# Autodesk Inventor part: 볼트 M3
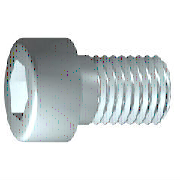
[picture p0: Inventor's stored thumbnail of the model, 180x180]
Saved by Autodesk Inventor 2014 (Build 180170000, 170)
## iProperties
IsCustomPart: 0
Created: 2012-02
Part Number: 볼트 M3
Material: 스테인리스강
Description: 6각 소켓 머리 캡 나사
Document SubType Name: Modeling
Standard: ISO 4762
Designer: mduedu
Standard Revision: Fourth edition 2004-03-01
Standards Organization: ISO
Language: ko-KR
Size Designation: M3 x 8
Categories: <MemberInstance><Categories><Category DisplayName="조임쇠" InternalName="e4da775c-781d-43d5-af7c-5136215cf5a6" Mnemonic="FSTN"><Category DisplayName="볼트" InternalN
Density: 7.75 g/cm^3
Appearance: 반광택
Author: mduedu
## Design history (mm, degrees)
sketch "스케치1"
  geometry: L1 (-0.867, 0)-(8, 0); L2 (8, 0)-(8, 1.5); L3 (8, 1.5)-(1.25, 1.5); L4 (1.25, 1.5)-(0.943, 1.5); L5 (0.943, 1.5)-(0, 1.5); L6 (0, 1.5)-(0, 2.75); L7 (0, 2.75)-(-3, 2.75); L8 (-3, 2.75)-(-3, 1.443); L9 (-3, 1.443)-(-1.7, 1.443); L10 (-1.7, 1.443)-(-0.867, 0); L11 (-5.2, 0)-(10.2, 0) reference; L12 (0, -0.55)-(0, 3.3) reference; L13 (1.25, 1.5)-(0, 1.5)
  constraints: 22 end point, 6 parallel, 2 collinear, 2 perpendicular, 1 horizontal, 1 point on line
  dimensions: "d1" = 6.75 distance from line of L3.end L2 (= GEL); "d2" = 0.30683 distance of L4.end L3.end (computed from GAL); "d3" = 3 distance between parallel lines of L8 L6 (= KOH); "d4" = 1.3 distance of L8.end L9.end (= INTI); "d5" = 60 deg angle of L10 L1; "d6" = 3 diameter of L3 L1 (= GD); "d7" = 3 diameter of L5 L1 (= BDM); "d8" = 2.88675 diameter of L9 L1 (= 1.1547 x SW); "d9" = 5.5 diameter of L7 L1 (= KOD); "d26" = 8 distance between parallel lines of L12 L2 (= NLG)
revolve "본체" sketch "스케치1" stored, may be unused: angle "d10" = 90 deg
sketch "스케치2"
  geometry: L1 (0, -3.85)-(0, 3.85) reference; L2 (-3.85, 0)-(3.85, 0) reference; L3 (1.443, 0)-(0.722, -1.25); L4 (0.722, -1.25)-(-0.722, -1.25); L5 (-0.722, -1.25)-(-1.443, 0); L6 (-1.443, 0)-(-0.722, 1.25); L7 (-0.722, 1.25)-(0.722, 1.25); L8 (0.722, 1.25)-(1.443, 0); 2 further points
  constraints: 12 end point, 1 coincident, 1 horizontal alignment, 1 point on line, 12 other
extrude "슬롯" join sketch "스케치2" stored distance "d11" = 10; taper "d12" = 0 deg
workplane "Work Plane1"
fillet "Fillet2" dims "d30" = 0.1 (= R)
body "Solid1"
fillet "모깎기1" dims "d17" = 0.3 (= RR)
feature "스레드" dims "d13" = 6.75 (= GEL), "d14" = 0
chamfer "모따기1" distance "d15" = 0.30673 (= -0.5 x SPD + 0.5 x GD); stored, may be unused: second distance "d16" = 0.30673 (= GUL), angle "d27" = 45 deg
other parameters: "GD" = 3 [user parameter; used in 2 equation terms], "NLG" = 8 [user parameter; used in 1 equation term], "GEL" = 6.75 [user parameter; used in 2 equation terms], "KOD" = 5.5 [user parameter; used in 1 equation term], "KOH" = 3 [user parameter; used in 1 equation term], "INTI" = 1.3 [user parameter; used in 1 equation term], "GAL" = 0.30673 (= 0.61345 x PTC) [user parameter; used in 1 equation term], "GUL" = 0.30673 (= 0.61345 x PTC) [user parameter; used in 1 equation term], "BDM" = 3 (= NND) [user parameter; used in 1 equation term], "SW" = 2.5 [user parameter; used in 2 equation terms], "RR" = 0.3 [user parameter; used in 1 equation term], "SPD" = 2.38655 (= NND - 1.2269 x PTC) [user parameter; used in 1 equation term], "d19" = 0, "d28" = 0, "d29" = 0, "R" = 0.1 [user parameter; used in 1 equation term], "TOA" = 30 deg [user parameter], "GD1" = 2.38655 (= THREADDIA - 1.2269 x PTC) [user parameter], "THREADDIA" = 3 [user parameter; used in 1 equation term], "FAWI" = 45 deg [user parameter], "PTC" = 0.5 [user parameter; used in 5 equation terms], "NND" = 3 [user parameter; used in 2 equation terms], "E0" = 2.8875 (= 1.155 x SW) [user parameter]
